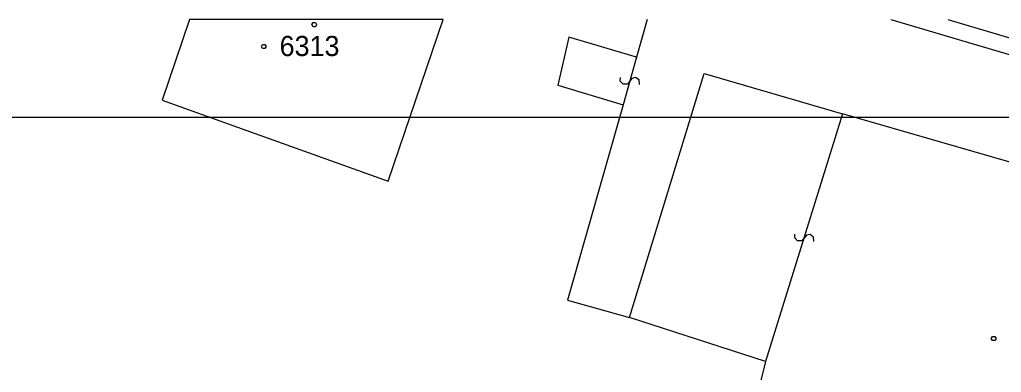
# Model space of a CAD drawing. Extents: x -888468 to -888310, y -1023047 to -1022832.
# Drawn here: x -888428.39 to -888391.81, y -1022844.79 to -1022831.64 of the extents above; entities that cross this region are included whole.
import ezdxf

# ---------------------------------------------------------------- set-up
doc = ezdxf.new("R2010")
doc.units = 0
for name, color, linetype in [('Formát', 7, 'Continuous'), ('Implicitní', 7, 'Continuous'), ('KN stav', 7, 'Continuous')]:
    doc.layers.add(name, color=color, linetype=linetype)

# ---------------------------------------------------------------- blocks, each defined once
blk = doc.blocks.new('402')
at = {"layer": 'Implicitní'}
blk.add_lwpolyline([(0.9, 1.5), (1.8, 0), (0.9, -1.5), (-0.9, -1.5), (-1.8, 0), (-0.9, 1.5), (0.9, 1.5)], dxfattribs=at)
blk = doc.blocks.new('2182')
at = {"layer": 'Implicitní'}
blk.add_lwpolyline([(0.5, 7.5), (-2.6, 6.4), (-3.7, 3.4), (-2.3, 0.9), (2.7, -1.1), (3.7, -4.1), (2.1, -6.8), (-0.5, -7.5)], dxfattribs=at)

msp = doc.modelspace()

# ---------------------------------------------------------------- linework, layer by layer
at = {"layer": 'Formát'}
msp.add_lwpolyline([(-888461.961, -1022835.294), (-888461.961, -1023045.294), (-888313.461, -1023045.294), (-888313.461, -1022835.294)], close=True, dxfattribs=at)
at = {"layer": 'KN stav'}
for p, q in [((-888412.61, -1022831.642), (-888422.063, -1022831.642)), ((-888405.003, -1022831.642), (-888405.4, -1022833.04)), ((-888405.4, -1022833.04), (-888405.9, -1022834.82)), ((-888397.72, -1022835.16), (-888400.59, -1022844.39)), ((-888380.33, -1022840.19), (-888397.72, -1022835.16)), ((-888400.59, -1022844.39), (-888405.66, -1022842.75))]:
    msp.add_line(p, q, dxfattribs=at)
for points in [[(-888422.063, -1022831.642), (-888423.08, -1022834.65), (-888414.65, -1022837.67), (-888412.61, -1022831.642)], [(-888395.921, -1022831.642), (-888366.39, -1022840.38), (-888371, -1022854.84), (-888379.9, -1022859.86), (-888386.45, -1022864.92), (-888386.7, -1022880.1), (-888389.13, -1022894.87), (-888391.86, -1022903.43), (-888393.66, -1022903.02), (-888399.68, -1022922.16), (-888387.05, -1022926.87), (-888374.19, -1022930.1), (-888372.02, -1022930.99), (-888351.3, -1022937.61), (-888350.91, -1022937.53), (-888346.06, -1022939.2)], [(-888393.799, -1022831.642), (-888366.24, -1022839.82)], [(-888405.4, -1022833.04), (-888407.92, -1022832.3), (-888408.33, -1022834.08), (-888405.9, -1022834.82)], [(-888405.9, -1022834.82), (-888407.97, -1022842.1), (-888405.66, -1022842.75), (-888402.88, -1022833.65), (-888397.72, -1022835.16)], [(-888400.59, -1022844.39), (-888401.25, -1022847.03), (-888383.88, -1022852.29), (-888380.33, -1022840.19)]]:
    msp.add_lwpolyline(points, dxfattribs=at)

# ---------------------------------------------------------------- block references
at = {"layer": 'KN stav', "xscale": 0.05, "yscale": 0.05000000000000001}
for p in [(-888417.41, -1022831.83), (-888419.29, -1022832.65), (-888392.09, -1022843.53)]:
    msp.add_blockref('402', p, dxfattribs=at)
at = {"layer": 'KN stav'}
for p, xscale, yscale, rotation in [((-888405.65, -1022833.93), 0.05000000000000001, 0.05, -105.835922), ((-888399.15, -1022839.78), 0.05, 0.05000000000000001, -107.268317)]:
    msp.add_blockref('2182', p, dxfattribs=dict(at, xscale=xscale, yscale=yscale, rotation=rotation))

# ---------------------------------------------------------------- texts
msp.add_text('6313', height=0.75, dxfattribs=at).set_placement((-888418.7, -1022833))

doc.saveas('drawing.dxf')
